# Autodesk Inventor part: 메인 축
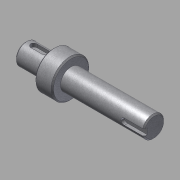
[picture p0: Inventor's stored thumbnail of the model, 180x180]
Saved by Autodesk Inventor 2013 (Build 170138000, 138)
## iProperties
Created: 2014-10
Part Number: 메인 축
Document SubType Name: Modeling
Designer: KYOUNG IL JANG
Density: 7.86 g/cm^3
Mass: 230.24 g
Surface Area: 74.3518 cm^2
Volume: 29.2926 cm^3
Material: 강철, 연강
d0: 17.000 mm
d1: 30.000 mm
d2: 22.000 mm
d5: 17.000 mm
d6: 1.000 mm
d9: 5.000 mm
d10: 14.000 mm
d11: 4.000 mm
d12: 3.000 mm
d13: 0.00 deg
d14: 5.000 mm
d15: 18.000 mm
d16: 3.000 mm
d17: 0.00 deg
d19: 80.000 mm
d3: 65.997 mm
Author: SeoGD™ [www.esajin.kr]
Revision Number: 1
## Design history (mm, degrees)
sketch "스케치1"
  geometry: L1 (10.497, -57.5)-(112.497, -57.5); L2 (10.497, -66)-(32.497, -66); L3 (32.497, -72.5)-(46.5, -72.5); L4 (46.5, -66)-(112.497, -66); L5 (112.497, -66)-(112.497, -57.5); L6 (10.497, -66)-(10.497, -57.5); L7 (46.5, -69.749)-(46.5, -45.251) reference; L8 (46.5, -72.5)-(46.5, -66); L9 (32.497, -72.5)-(32.497, -66); L10 (32.497, -35)-(32.497, -80) reference; 3 further points
  constraints: 16 end point, 3 point on line, 2 parallel, 2 perpendicular, 1 collinear, 1 horizontal, 1 midpoint
  dimensions: "d0" = 17 diameter of L4 L1; "d1" = 30 diameter of L3 L1; "d2" = 22 distance of L2.start L2.end; "d3" = 65.99692 distance of L4.start L4.end (derived); "d5" = 17 diameter of L2 L1; "d19" = 80 distance between parallel lines of L5 L9
revolve "회전1" sketch "스케치1" stored, may be unused: angle "d4" = 90 deg
chamfer "모따기1" distance "d6" = 1; stored, may be unused: second distance "d7" = 2, angle "d8" = 45 deg
node "작업 평면1"
sketch "스케치2"
  geometry: L1 (-11, -7.5)-(-11, 7.5) reference; L2 (-4.5, 2.5)-(4.5, 2.5); L3 (4.5, -2.5)-(-4.5, -2.5); A1 r 2.5 centre (4.5, 0) between (4.5, -2.5) and (4.5, 2.5); A2 r 2.5 centre (-4.5, 0) between (-4.5, 2.5) and (-4.5, -2.5); 2 further points
  constraints: 4 end point, 4 point on circle, 4 tangent, 2 centre point, 1 horizontal alignment, 1 midpoint, 1 parallel, 1 perpendicular
  dimensions: "d9" = 5 distance between parallel lines of L3 L2; "d10" = 14 dimension on A1 A2; "d11" = 4 distance edge to line of A2 L1
extrude "돌출1" cut sketch "스케치2" distance "d12" = 3; taper "d13" = 0 deg
node "작업 평면2"
sketch "스케치3"
  geometry: L1 (32.998, 7.5)-(32.998, -7.5) reference; L2 (32.998, 2.5)-(17.498, 2.5); L3 (17.498, -2.5)-(32.998, -2.5); A1 r 2.5 centre (17.498, 0) between (17.498, 2.5) and (17.498, -2.5); 2 further points
  constraints: 4 end point, 2 perpendicular, 2 point on circle, 2 point on line, 2 tangent, 1 centre point, 1 horizontal alignment, 1 midpoint
  dimensions: "d14" = 5 distance between parallel lines of L3 L2; "d15" = 18 dimension on A1 L1
extrude "돌출2" cut sketch "스케치3" distance "d16" = 3; taper "d17" = 0 deg
node "솔리드1"
node "참조4"
node "참조5"
